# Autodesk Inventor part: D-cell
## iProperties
Shininess: 64.0
Angle Display Precision: 2
Document Length Units: 11272
Document Angle Units: 11279
Document Time Units: 11290
Document Mass Units: 11286
Document Length Units Precision: 3
Document Angle Units Precision: 2
Created: 2002-02
Part Number: D-cell
Document SubType Name: Modeling
Designer: Ron Crain
Catalog Web Link: http://www.arken.net
Density: 0.0
Volumn: 0.0
Area: 0.0
PropertySet Name: Model Information
Control State: 0
Master: False
Checked Out: False
Author: Ron Crain
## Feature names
1. Revolution1
2. Revolution3
3. Fillet1
